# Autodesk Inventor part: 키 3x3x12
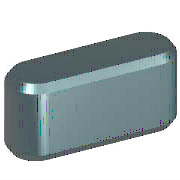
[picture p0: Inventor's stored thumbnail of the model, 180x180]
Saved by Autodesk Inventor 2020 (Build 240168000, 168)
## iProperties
Created: 2012-02
Part Number: 키 3x3x12
Material: 강철, 연강
Description: 키 및 해당 키홈
Document SubType Name: Modeling
Standard: KS B 1311
Designer: mduedu
Standards Organization: KS
Language: ko-KR
Size Designation: 3 x 3 x 12
Categories: <MemberInstance><Categories><Category DisplayName="샤프트 부품" InternalName="7f7aeb1f-a693-4053-b835-cee3144e0d98" Mnemonic="SHFT"><Category DisplayName="키" Interna
Density: 1 g/cm^3
Appearance: 노란색
IsCustomPart: 1
Author: mduedu
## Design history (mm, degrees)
workplane "Work Plane1"
workplane "Work Plane2"
sketch "스케치1"
  geometry: L1 (1.5, 1.5)-(10.5, 1.5); L2 (10.5, -1.5)-(1.5, -1.5); L3 (0, 9.4)-(0, -7.4) reference; L4 (-5, 0)-(30, 0) reference; L5 (12, 0)-(12, 7); A1 r 1.5 centre (1.5, 0) between (1.5, 1.5) and (1.5, -1.5); A2 r 1.5 centre (10.5, 0) between (10.5, -1.5) and (10.5, 1.5)
  constraints: 6 end point, 5 point on circle, 4 tangent, 3 point on line, 2 centre point, 1 horizontal, 1 parallel, 1 perpendicular
  dimensions: "d0" = 1.5 radius of A1 (= 0.5 x PB); "d13" = 1.5 radius of A2 (= 0.5 x PB); "d14" = 12 distance between parallel lines of L5 L3 (= NLG)
extrude "본체1" new body sketch "스케치1" taper "d3" = 0 deg; stored distance "d4" = 10
workplane "Work Plane3"
body "Solid1"
chamfer "모따기1" distance "d8" = 0.25 (= PHH); stored, may be unused: second distance "d9" = 0.25 (= PHH), angle "d15" = 45 deg
other parameters: "d1" = -1.8 (= -PNT), "d2" = 1.2 (= PH - PNT), "NLG" = 12 [user parameter; used in 3 equation terms], "PB" = 3 [user parameter; used in 2 equation terms], "PNT" = 1.8 [user parameter; used in 2 equation terms], "PH" = 3 [user parameter; used in 1 equation term], "PHH" = 0.25 [user parameter; used in 2 equation terms], "d10" = 0, "d16" = 0, "d17" = 0, "d18" = 0, "WDMIN" = 8 [user parameter], "PLB2" = 12 (= NLG) [user parameter], "PLB1" = 12 (= NLG) [user parameter], "RR" = 0.08 [user parameter], "PUEB" = 1.4 [user parameter]
